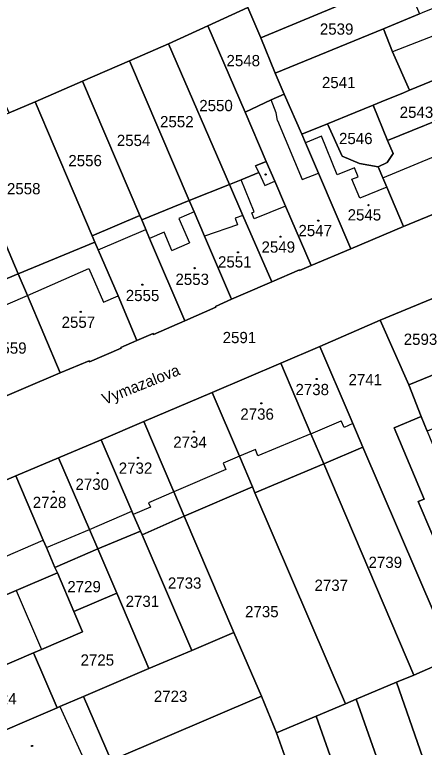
# Model space of a CAD drawing. Extents: x -596233 to -595156, y -1161235 to -1159375.
# Drawn here: x -595764.4 to -595702.6, y -1160730 to -1160619.4 of the extents above; entities that cross this region are included whole.
import ezdxf

# ---------------------------------------------------------------- set-up
doc = ezdxf.new("R2010")
doc.units = 0
for name, color, linetype in [('KN_CAR_KR', 7, 'Continuous'), ('KN_KULTURY', 7, 'Continuous'), ('KN_PARC_CIS_POZ', 7, 'Continuous'), ('KN_PARC_CIS_STAV', 7, 'Continuous'), ('KN_PARC_PLOCHA', 7, 'Continuous'), ('KN_ULICE', 7, 'Continuous'), ('parcely_l', 7, 'Continuous')]:
    doc.layers.add(name, color=color, linetype=linetype)

msp = doc.modelspace()

# ---------------------------------------------------------------- linework, layer by layer
at = {"layer": 'KN_CAR_KR'}
for points in [[(-595695.86, -1160620.52), (-595707.37, -1160625.04)], [(-595724.92, -1160634.21), (-595725.69, -1160632.26)], [(-595724.73, -1160635.4), (-595724.92, -1160634.21)], [(-595724.73, -1160635.4), (-595720.98, -1160644.31)], [(-595718.09, -1160637.77), (-595720.49, -1160638.76)], [(-595715.7, -1160643.59), (-595718.09, -1160637.77)], [(-595708.81, -1160644.05), (-595693.47, -1160637.66)], [(-595727.53, -1160643.25), (-595726.61, -1160645.18)], [(-595720.98, -1160644.31), (-595718.55, -1160643.32)], [(-595713.12, -1160642.53), (-595715.7, -1160643.59)], [(-595712.56, -1160643.88), (-595713.12, -1160642.53)], [(-595728.26, -1160649.17), (-595730.19, -1160644.34)], [(-595726.61, -1160645.18), (-595725.14, -1160644.55)], [(-595713.49, -1160644.26), (-595712.56, -1160643.88)], [(-595712.31, -1160647.13), (-595713.49, -1160644.26)], [(-595708.22, -1160645.45), (-595712.31, -1160647.13)], [(-595723.5, -1160648.34), (-595728.22, -1160650.22)], [(-595737.28, -1160649.19), (-595739.58, -1160650.17)], [(-595729.93, -1160649.73), (-595731.11, -1160650.14)], [(-595728.59, -1160649.3), (-595728.26, -1160649.17)], [(-595728.22, -1160650.22), (-595728.59, -1160649.3)], [(-595739.58, -1160650.17), (-595738.01, -1160653.86)], [(-595730.76, -1160651.14), (-595735.71, -1160652.87)], [(-595731.11, -1160650.14), (-595730.76, -1160651.14)], [(-595751.75, -1160654.9), (-595744.59, -1160651.82)], [(-595741.8, -1160652.24), (-595744.01, -1160653.18)], [(-595740.63, -1160654.99), (-595741.8, -1160652.24)], [(-595740.63, -1160654.99), (-595738.01, -1160653.86)], [(-595762.44, -1160661.8), (-595753.19, -1160657.75)], [(-595753.19, -1160657.75), (-595750.97, -1160662.81)], [(-595771.92, -1160665.87), (-595762.44, -1160661.8)], [(-595750.97, -1160662.81), (-595748.76, -1160661.84)], [(-595719.68, -1160682.67), (-595715.09, -1160680.74)], [(-595714.68, -1160681.73), (-595715.09, -1160680.74)], [(-595713.34, -1160681.15), (-595714.68, -1160681.73)], [(-595719.68, -1160682.67), (-595727.66, -1160686.01)], [(-595728.05, -1160685.08), (-595730.45, -1160686.08)], [(-595727.66, -1160686.01), (-595728.05, -1160685.08)], [(-595730.45, -1160686.08), (-595732.9, -1160687.14)], [(-595732.9, -1160687.14), (-595732.5, -1160688.06)], [(-595732.5, -1160688.06), (-595740.35, -1160691.46)], [(-595740.35, -1160691.46), (-595744.15, -1160693.1)], [(-595744.15, -1160693.1), (-595743.87, -1160693.75)], [(-595753.08, -1160697.13), (-595746.68, -1160694.38)], [(-595743.87, -1160693.75), (-595746.47, -1160694.87)], [(-595759.57, -1160699.85), (-595753.08, -1160697.13)], [(-595767.32, -1160701.86), (-595760.04, -1160698.74)], [(-595764.14, -1160706.35), (-595760.31, -1160715.27)], [(-595757.55, -1160723.87), (-595753.17, -1160733.47)]]:
    msp.add_lwpolyline(points, dxfattribs=at)
at = {"layer": 'KN_KULTURY'}
for centre, radius in [((-595726.51, -1160643.54), 0.09), ((-595726.51, -1160643.54), 0.0398), ((-595711, -1160648.17), 0.09), ((-595711, -1160648.17), 0.0398), ((-595718.57, -1160650.5), 0.09), ((-595718.57, -1160650.5), 0.0398), ((-595724.27, -1160652.93), 0.09), ((-595724.27, -1160652.93), 0.0398), ((-595730.68, -1160655.28), 0.09), ((-595730.68, -1160655.28), 0.0398), ((-595737.22, -1160657.69), 0.09), ((-595737.22, -1160657.69), 0.0398), ((-595745.09, -1160660.18), 0.09), ((-595745.09, -1160660.18), 0.0398), ((-595754.4, -1160664.28), 0.09), ((-595754.4, -1160664.28), 0.0398), ((-595718.81, -1160674.41), 0.09), ((-595718.81, -1160674.41), 0.0398), ((-595727.15, -1160678.09), 0.09), ((-595727.15, -1160678.09), 0.0398), ((-595737.3, -1160682.37), 0.09), ((-595737.3, -1160682.37), 0.0398), ((-595745.75, -1160686.32), 0.09), ((-595745.75, -1160686.32), 0.0398), ((-595751.84, -1160688.63), 0.09), ((-595751.84, -1160688.63), 0.0398), ((-595758.47, -1160691.42), 0.09), ((-595758.47, -1160691.42), 0.0398), ((-595761.73, -1160729.81), 0.09), ((-595761.73, -1160729.81), 0.0398)]:
    msp.add_circle(centre, radius, dxfattribs=at)
at = {"layer": 'KN_PARC_PLOCHA'}
for points in [[(-595735.3, -1160604.49), (-595731.23, -1160613.58), (-595729.21, -1160618.3), (-595735.24, -1160621.08), (-595741.16, -1160623.81), (-595747.02, -1160626.37), (-595754.12, -1160629.47), (-595761.28, -1160632.55), (-595765.17, -1160634.23), (-595770.95, -1160621.41), (-595774.09, -1160614.44), (-595760.01, -1160608.41), (-595748.98, -1160603.72), (-595737.74, -1160599.11), (-595736.97, -1160600.8), (-595736.1, -1160602.72)], [(-595708, -1160614.86), (-595727.25, -1160622.89), (-595729.21, -1160618.3), (-595731.23, -1160613.58), (-595714.79, -1160606.77), (-595711, -1160605.2)], [(-595685.05, -1160622.72), (-595699.52, -1160628.65), (-595704.82, -1160630.82), (-595707.37, -1160625.04), (-595708.75, -1160621.53), (-595703.31, -1160619.29), (-595702.83, -1160619.09), (-595697.24, -1160616.79), (-595688.8, -1160613.32)], [(-595703.31, -1160619.29), (-595708.75, -1160621.53), (-595725.07, -1160628.25), (-595727.25, -1160622.89), (-595708, -1160614.86), (-595705.6, -1160613.86)], [(-595727.25, -1160622.89), (-595725.07, -1160628.25), (-595723.69, -1160631.42), (-595725.69, -1160632.26), (-595729.61, -1160634.15), (-595735.24, -1160621.08), (-595729.21, -1160618.3)], [(-595729.61, -1160634.15), (-595726.42, -1160641.56), (-595728.01, -1160642.25), (-595727.53, -1160643.25), (-595730.19, -1160644.34), (-595731.96, -1160645.05), (-595741.16, -1160623.81), (-595735.24, -1160621.08)], [(-595704.82, -1160630.82), (-595705.72, -1160631.19), (-595709.1, -1160632.57), (-595710.31, -1160633.07), (-595713, -1160634.17), (-595717.18, -1160635.88), (-595721.05, -1160637.47), (-595723.69, -1160631.42), (-595725.07, -1160628.25), (-595708.75, -1160621.53), (-595707.37, -1160625.04)], [(-595731.96, -1160645.05), (-595738.02, -1160647.45), (-595747.02, -1160626.37), (-595741.16, -1160623.81)], [(-595738.02, -1160647.45), (-595745.2, -1160650.39), (-595745.48, -1160649.74), (-595754.12, -1160629.47), (-595747.02, -1160626.37)], [(-595696.11, -1160633.52), (-595696.69, -1160633.76), (-595708.12, -1160638.41), (-595710.31, -1160633.07), (-595709.1, -1160632.57), (-595705.72, -1160631.19), (-595704.82, -1160630.82), (-595699.52, -1160628.65), (-595698.57, -1160630.94), (-595697.19, -1160630.37)], [(-595678.53, -1160638.71), (-595679.29, -1160640.57), (-595682.45, -1160641.9), (-595682.48, -1160641.83), (-595705.69, -1160651.41), (-595708.22, -1160645.45), (-595708.81, -1160644.05), (-595709.52, -1160642.37), (-595708.18, -1160641.71), (-595707.27, -1160640.35), (-595708.12, -1160638.41), (-595696.69, -1160633.76), (-595696.11, -1160633.52), (-595691.34, -1160631.58), (-595682.89, -1160628.14), (-595679.85, -1160635.65), (-595679.77, -1160635.62)], [(-595745.48, -1160649.74), (-595752.65, -1160652.8), (-595761.28, -1160632.55), (-595754.12, -1160629.47)], [(-595721.05, -1160637.47), (-595720.49, -1160638.76), (-595718.55, -1160643.32), (-595713.68, -1160654.78), (-595719.65, -1160657.3), (-595723.5, -1160648.34), (-595725.14, -1160644.55), (-595726.42, -1160641.56), (-595729.61, -1160634.15), (-595725.69, -1160632.26), (-595723.69, -1160631.42)], [(-595752.65, -1160652.8), (-595752.25, -1160653.74), (-595763.83, -1160658.51), (-595772.74, -1160637.53), (-595765.17, -1160634.23), (-595761.28, -1160632.55)], [(-595708.12, -1160638.41), (-595707.27, -1160640.35), (-595708.18, -1160641.71), (-595709.52, -1160642.37), (-595712.35, -1160641.86), (-595714.95, -1160640.78), (-595717.18, -1160635.88), (-595713, -1160634.17), (-595710.31, -1160633.07)], [(-595709.52, -1160642.37), (-595708.81, -1160644.05), (-595708.22, -1160645.45), (-595705.69, -1160651.41), (-595713.68, -1160654.78), (-595718.55, -1160643.32), (-595720.49, -1160638.76), (-595721.05, -1160637.47), (-595717.18, -1160635.88), (-595714.95, -1160640.78), (-595712.35, -1160641.86)], [(-595763.83, -1160658.51), (-595774.97, -1160663.23), (-595777.9, -1160656.33), (-595780.82, -1160649.48), (-595783.88, -1160642.28), (-595772.74, -1160637.53)], [(-595719.65, -1160657.3), (-595721.38, -1160658.03), (-595721.42, -1160657.93), (-595725.59, -1160659.74), (-595729.93, -1160649.73), (-595731.96, -1160645.05), (-595730.19, -1160644.34), (-595727.53, -1160643.25), (-595728.01, -1160642.25), (-595726.42, -1160641.56), (-595725.14, -1160644.55), (-595723.5, -1160648.34)], [(-595725.59, -1160659.74), (-595729.87, -1160661.59), (-595731.65, -1160662.38), (-595735.71, -1160652.87), (-595737.28, -1160649.19), (-595738.02, -1160647.45), (-595731.96, -1160645.05), (-595729.93, -1160649.73)], [(-595731.65, -1160662.38), (-595734.08, -1160663.45), (-595734.02, -1160663.59), (-595738.7, -1160665.63), (-595744.01, -1160653.18), (-595744.59, -1160651.82), (-595745.2, -1160650.39), (-595738.02, -1160647.45), (-595737.28, -1160649.19), (-595735.71, -1160652.87)], [(-595745.2, -1160650.39), (-595744.59, -1160651.82), (-595744.01, -1160653.18), (-595738.7, -1160665.63), (-595743.42, -1160667.69), (-595743.48, -1160667.55), (-595745.91, -1160668.61), (-595748.76, -1160661.84), (-595751.75, -1160654.9), (-595752.25, -1160653.74), (-595752.65, -1160652.8), (-595745.48, -1160649.74)], [(-595745.91, -1160668.61), (-595748.34, -1160669.68), (-595748.3, -1160669.78), (-595753.08, -1160671.81), (-595753.14, -1160671.66), (-595757.48, -1160673.47), (-595762.44, -1160661.8), (-595763.83, -1160658.51), (-595752.25, -1160653.74), (-595751.75, -1160654.9), (-595748.76, -1160661.84)], [(-595757.48, -1160673.47), (-595768.59, -1160678.23), (-595771.39, -1160671.63), (-595772.59, -1160668.83), (-595774.97, -1160663.23), (-595763.83, -1160658.51), (-595762.44, -1160661.8)], [(-595696.04, -1160671.68), (-595704.92, -1160675.31), (-595709.22, -1160665.55), (-595699.97, -1160661.68)], [(-595704.92, -1160675.31), (-595703.06, -1160680.07), (-595707.1, -1160681.78), (-595702.62, -1160692.55), (-595703.52, -1160692.93), (-595699.39, -1160702.59), (-595694.62, -1160700.78), (-595693.12, -1160704.73), (-595690.38, -1160712.25), (-595690.11, -1160713.15), (-595698.19, -1160716.57), (-595711.83, -1160684.68), (-595713.34, -1160681.15), (-595713.75, -1160680.18), (-595718.33, -1160669.48), (-595709.22, -1160665.55)], [(-595686.01, -1160675.72), (-595702.12, -1160682.29), (-595703.06, -1160680.07), (-595704.92, -1160675.31), (-595696.04, -1160671.68), (-595694.19, -1160670.91), (-595688.87, -1160668.73), (-595687.63, -1160671.58)], [(-595711.83, -1160684.68), (-595717.74, -1160687.22), (-595719.68, -1160682.67), (-595724.22, -1160672), (-595718.33, -1160669.48), (-595713.75, -1160680.18), (-595713.34, -1160681.15)], [(-595717.74, -1160687.22), (-595728.11, -1160691.58), (-595728.48, -1160690.69), (-595730.45, -1160686.08), (-595734.58, -1160676.43), (-595724.22, -1160672), (-595719.68, -1160682.67)], [(-595728.48, -1160690.69), (-595738.79, -1160695.14), (-595740.35, -1160691.46), (-595744.88, -1160680.84), (-595734.58, -1160676.43), (-595730.45, -1160686.08)], [(-595738.79, -1160695.14), (-595745.14, -1160697.96), (-595745.38, -1160697.41), (-595746.47, -1160694.87), (-595746.68, -1160694.38), (-595751.31, -1160683.59), (-595744.88, -1160680.84), (-595740.35, -1160691.46)], [(-595702.12, -1160682.29), (-595699.89, -1160687.83), (-595696.29, -1160696.39), (-595694.62, -1160700.78), (-595699.39, -1160702.59), (-595703.52, -1160692.93), (-595702.62, -1160692.55), (-595707.1, -1160681.78), (-595703.06, -1160680.07)], [(-595745.38, -1160697.41), (-595751.83, -1160700.05), (-595753.08, -1160697.13), (-595757.76, -1160686.32), (-595751.31, -1160683.59), (-595746.68, -1160694.38), (-595746.47, -1160694.87)], [(-595698.19, -1160716.57), (-595700.83, -1160717.68), (-595704.17, -1160719.1), (-595717.74, -1160687.22), (-595711.83, -1160684.68)], [(-595751.83, -1160700.05), (-595758.28, -1160702.86), (-595759.57, -1160699.85), (-595760.04, -1160698.74), (-595764.2, -1160689.05), (-595757.76, -1160686.32), (-595753.08, -1160697.13)], [(-595704.17, -1160719.1), (-595706.79, -1160720.2), (-595712.84, -1160722.76), (-595714.48, -1160723.45), (-595728.11, -1160691.58), (-595717.74, -1160687.22)], [(-595758.28, -1160702.86), (-595757.92, -1160703.68), (-595764.14, -1160706.35), (-595765.2, -1160706.8), (-595777.73, -1160712.2), (-595783.98, -1160697.54), (-595764.2, -1160689.05), (-595760.04, -1160698.74), (-595759.57, -1160699.85)], [(-595728.11, -1160691.58), (-595714.48, -1160723.45), (-595718.89, -1160725.32), (-595724.86, -1160727.84), (-595727.15, -1160722.31), (-595731.3, -1160712.67), (-595738.79, -1160695.14), (-595728.48, -1160690.69)], [(-595731.3, -1160712.67), (-595737.66, -1160715.38), (-595745.14, -1160697.96), (-595738.79, -1160695.14)], [(-595745.14, -1160697.96), (-595737.66, -1160715.38), (-595744.11, -1160718.13), (-595748.97, -1160706.75), (-595751.83, -1160700.05), (-595745.38, -1160697.41)], [(-595748.97, -1160706.75), (-595755.42, -1160709.52), (-595757.92, -1160703.68), (-595758.28, -1160702.86), (-595751.83, -1160700.05)], [(-595755.42, -1160709.52), (-595754.1, -1160712.6), (-595760.31, -1160715.27), (-595761.49, -1160715.77), (-595773.94, -1160721.11), (-595777.73, -1160712.2), (-595765.2, -1160706.8), (-595764.14, -1160706.35), (-595757.92, -1160703.68)], [(-595744.11, -1160718.13), (-595753.97, -1160722.33), (-595757.55, -1160723.87), (-595757.97, -1160724.05), (-595761.49, -1160715.77), (-595760.31, -1160715.27), (-595754.1, -1160712.6), (-595755.42, -1160709.52), (-595748.97, -1160706.75)], [(-595727.15, -1160722.31), (-595749.37, -1160731.83), (-595749.78, -1160732.01), (-595753.97, -1160722.33), (-595744.11, -1160718.13), (-595737.66, -1160715.38), (-595731.3, -1160712.67)], [(-595757.97, -1160724.05), (-595770.41, -1160729.4), (-595773.94, -1160721.11), (-595761.49, -1160715.77)], [(-595691.05, -1160745.5), (-595690.33, -1160747.56), (-595696.49, -1160749.65), (-595706.79, -1160720.2), (-595704.17, -1160719.1), (-595700.83, -1160717.68)], [(-595696.49, -1160749.65), (-595702.65, -1160751.74), (-595712.84, -1160722.76), (-595706.79, -1160720.2)], [(-595749.78, -1160732.01), (-595753.17, -1160733.47), (-595766.25, -1160739.11), (-595770.41, -1160729.4), (-595757.97, -1160724.05), (-595757.55, -1160723.87), (-595753.97, -1160722.33)], [(-595724.86, -1160727.84), (-595723.37, -1160732.08), (-595745.36, -1160741.5), (-595749.37, -1160731.83), (-595727.15, -1160722.31)], [(-595702.65, -1160751.74), (-595708.82, -1160753.83), (-595718.89, -1160725.32), (-595714.48, -1160723.45), (-595712.84, -1160722.76)], [(-595708.82, -1160753.83), (-595714.97, -1160756.05), (-595718.37, -1160746.3), (-595720.88, -1160739.16), (-595723.37, -1160732.08), (-595724.86, -1160727.84), (-595718.89, -1160725.32)]]:
    msp.add_lwpolyline(points, close=True, dxfattribs=at)
for points in [[(-595768.59, -1160678.23), (-595757.48, -1160673.47), (-595753.14, -1160671.66), (-595753.08, -1160671.81), (-595748.3, -1160669.78), (-595748.34, -1160669.68), (-595745.91, -1160668.61), (-595743.48, -1160667.55), (-595743.42, -1160667.69), (-595738.7, -1160665.63), (-595734.02, -1160663.59), (-595734.08, -1160663.45), (-595731.65, -1160662.38), (-595729.87, -1160661.59), (-595725.59, -1160659.74), (-595721.42, -1160657.93), (-595721.38, -1160658.03), (-595719.65, -1160657.3), (-595713.68, -1160654.78), (-595705.69, -1160651.41), (-595682.48, -1160641.83)], [(-595699.97, -1160661.68), (-595709.22, -1160665.55), (-595718.33, -1160669.48), (-595724.22, -1160672), (-595734.58, -1160676.43), (-595744.88, -1160680.84), (-595751.31, -1160683.59), (-595757.76, -1160686.32), (-595764.2, -1160689.05), (-595783.98, -1160697.54)]]:
    msp.add_lwpolyline(points, dxfattribs=at)
at = {"layer": 'parcely_l'}
for points in [[(-595708, -1160614.86), (-595727.25, -1160622.89)], [(-595735.24, -1160621.08), (-595729.21, -1160618.3)], [(-595727.25, -1160622.89), (-595729.21, -1160618.3)], [(-595703.31, -1160619.29), (-595708.75, -1160621.53)], [(-595735.24, -1160621.08), (-595741.16, -1160623.81)], [(-595729.61, -1160634.15), (-595735.24, -1160621.08)], [(-595708.75, -1160621.53), (-595725.07, -1160628.25)], [(-595704.82, -1160630.82), (-595707.37, -1160625.04), (-595708.75, -1160621.53)], [(-595727.25, -1160622.89), (-595725.07, -1160628.25)], [(-595741.16, -1160623.81), (-595747.02, -1160626.37)], [(-595731.96, -1160645.05), (-595741.16, -1160623.81)], [(-595754.12, -1160629.47), (-595747.02, -1160626.37)], [(-595747.02, -1160626.37), (-595738.02, -1160647.45)], [(-595725.07, -1160628.25), (-595723.69, -1160631.42)], [(-595704.82, -1160630.82), (-595699.52, -1160628.65)], [(-595754.12, -1160629.47), (-595761.28, -1160632.55)], [(-595745.48, -1160649.74), (-595754.12, -1160629.47)], [(-595710.31, -1160633.07), (-595709.1, -1160632.57), (-595705.72, -1160631.19), (-595704.82, -1160630.82)], [(-595729.61, -1160634.15), (-595725.69, -1160632.26), (-595723.69, -1160631.42)], [(-595723.69, -1160631.42), (-595721.05, -1160637.47)], [(-595761.28, -1160632.55), (-595765.17, -1160634.23)], [(-595761.28, -1160632.55), (-595752.65, -1160652.8)], [(-595717.18, -1160635.88), (-595713, -1160634.17), (-595710.31, -1160633.07)], [(-595710.31, -1160633.07), (-595708.12, -1160638.41)], [(-595708.12, -1160638.41), (-595696.69, -1160633.76), (-595696.11, -1160633.52)], [(-595726.42, -1160641.56), (-595729.61, -1160634.15)], [(-595721.05, -1160637.47), (-595717.18, -1160635.88)], [(-595709.52, -1160642.37), (-595712.35, -1160641.86), (-595714.95, -1160640.78), (-595717.18, -1160635.88)], [(-595763.83, -1160658.51), (-595772.74, -1160637.53)], [(-595721.05, -1160637.47), (-595720.49, -1160638.76), (-595718.55, -1160643.32), (-595713.68, -1160654.78)], [(-595708.12, -1160638.41), (-595707.27, -1160640.35), (-595708.18, -1160641.71), (-595709.52, -1160642.37)], [(-595705.69, -1160651.41), (-595682.48, -1160641.83), (-595682.45, -1160641.9), (-595679.29, -1160640.57), (-595678.53, -1160638.71)], [(-595731.96, -1160645.05), (-595730.19, -1160644.34), (-595727.53, -1160643.25), (-595728.01, -1160642.25), (-595726.42, -1160641.56)], [(-595719.65, -1160657.3), (-595723.5, -1160648.34), (-595725.14, -1160644.55), (-595726.42, -1160641.56)], [(-595709.52, -1160642.37), (-595708.81, -1160644.05), (-595708.22, -1160645.45), (-595705.69, -1160651.41)], [(-595738.02, -1160647.45), (-595731.96, -1160645.05)], [(-595731.96, -1160645.05), (-595729.93, -1160649.73), (-595725.59, -1160659.74)], [(-595738.02, -1160647.45), (-595745.2, -1160650.39)], [(-595731.65, -1160662.38), (-595735.71, -1160652.87), (-595737.28, -1160649.19), (-595738.02, -1160647.45)], [(-595752.65, -1160652.8), (-595745.48, -1160649.74)], [(-595745.2, -1160650.39), (-595745.48, -1160649.74)], [(-595738.7, -1160665.63), (-595744.01, -1160653.18), (-595744.59, -1160651.82), (-595745.2, -1160650.39)], [(-595713.68, -1160654.78), (-595705.69, -1160651.41)], [(-595752.25, -1160653.74), (-595752.65, -1160652.8)], [(-595763.83, -1160658.51), (-595752.25, -1160653.74)], [(-595752.25, -1160653.74), (-595751.75, -1160654.9), (-595748.76, -1160661.84), (-595745.91, -1160668.61)], [(-595713.68, -1160654.78), (-595719.65, -1160657.3)], [(-595725.59, -1160659.74), (-595721.42, -1160657.93), (-595721.38, -1160658.03), (-595719.65, -1160657.3)], [(-595763.83, -1160658.51), (-595774.97, -1160663.23)], [(-595757.48, -1160673.47), (-595762.44, -1160661.8), (-595763.83, -1160658.51)], [(-595725.59, -1160659.74), (-595729.87, -1160661.59), (-595731.65, -1160662.38)], [(-595699.97, -1160661.68), (-595709.22, -1160665.55)], [(-595738.7, -1160665.63), (-595734.02, -1160663.59), (-595734.08, -1160663.45), (-595731.65, -1160662.38)], [(-595709.22, -1160665.55), (-595718.33, -1160669.48)], [(-595709.22, -1160665.55), (-595704.92, -1160675.31)], [(-595745.91, -1160668.61), (-595743.48, -1160667.55), (-595743.42, -1160667.69), (-595738.7, -1160665.63)], [(-595757.48, -1160673.47), (-595753.14, -1160671.66), (-595753.08, -1160671.81), (-595748.3, -1160669.78), (-595748.34, -1160669.68), (-595745.91, -1160668.61)], [(-595718.33, -1160669.48), (-595724.22, -1160672)], [(-595711.83, -1160684.68), (-595713.34, -1160681.15), (-595713.75, -1160680.18), (-595718.33, -1160669.48)], [(-595724.22, -1160672), (-595734.58, -1160676.43)], [(-595724.22, -1160672), (-595719.68, -1160682.67), (-595717.74, -1160687.22)], [(-595704.92, -1160675.31), (-595696.04, -1160671.68)], [(-595768.59, -1160678.23), (-595757.48, -1160673.47)], [(-595704.92, -1160675.31), (-595703.06, -1160680.07)], [(-595744.88, -1160680.84), (-595734.58, -1160676.43)], [(-595734.58, -1160676.43), (-595730.45, -1160686.08), (-595728.48, -1160690.69)], [(-595744.88, -1160680.84), (-595751.31, -1160683.59)], [(-595738.79, -1160695.14), (-595740.35, -1160691.46), (-595744.88, -1160680.84)], [(-595703.06, -1160680.07), (-595707.1, -1160681.78), (-595702.62, -1160692.55), (-595703.52, -1160692.93), (-595699.39, -1160702.59), (-595694.62, -1160700.78)], [(-595702.12, -1160682.29), (-595703.06, -1160680.07)], [(-595751.31, -1160683.59), (-595757.76, -1160686.32)], [(-595751.31, -1160683.59), (-595746.68, -1160694.38), (-595746.47, -1160694.87), (-595745.38, -1160697.41)], [(-595717.74, -1160687.22), (-595711.83, -1160684.68)], [(-595698.19, -1160716.57), (-595711.83, -1160684.68)], [(-595757.76, -1160686.32), (-595764.2, -1160689.05)], [(-595751.83, -1160700.05), (-595753.08, -1160697.13), (-595757.76, -1160686.32)], [(-595717.74, -1160687.22), (-595728.11, -1160691.58)], [(-595717.74, -1160687.22), (-595704.17, -1160719.1)], [(-595783.98, -1160697.54), (-595764.2, -1160689.05)], [(-595764.2, -1160689.05), (-595760.04, -1160698.74), (-595759.57, -1160699.85), (-595758.28, -1160702.86)], [(-595728.48, -1160690.69), (-595738.79, -1160695.14)], [(-595728.11, -1160691.58), (-595728.48, -1160690.69)], [(-595728.11, -1160691.58), (-595714.48, -1160723.45)], [(-595745.14, -1160697.96), (-595738.79, -1160695.14)], [(-595738.79, -1160695.14), (-595731.3, -1160712.67)], [(-595745.38, -1160697.41), (-595751.83, -1160700.05)], [(-595745.14, -1160697.96), (-595745.38, -1160697.41)], [(-595737.66, -1160715.38), (-595745.14, -1160697.96)], [(-595758.28, -1160702.86), (-595751.83, -1160700.05)], [(-595751.83, -1160700.05), (-595748.97, -1160706.75)], [(-595758.28, -1160702.86), (-595757.92, -1160703.68)], [(-595757.92, -1160703.68), (-595764.14, -1160706.35), (-595765.2, -1160706.8), (-595777.73, -1160712.2)], [(-595755.42, -1160709.52), (-595757.92, -1160703.68)], [(-595755.42, -1160709.52), (-595748.97, -1160706.75)], [(-595748.97, -1160706.75), (-595744.11, -1160718.13)], [(-595761.49, -1160715.77), (-595760.31, -1160715.27), (-595754.1, -1160712.6), (-595755.42, -1160709.52)], [(-595731.3, -1160712.67), (-595737.66, -1160715.38)], [(-595731.3, -1160712.67), (-595727.15, -1160722.31)], [(-595744.11, -1160718.13), (-595737.66, -1160715.38)], [(-595773.94, -1160721.11), (-595761.49, -1160715.77)], [(-595761.49, -1160715.77), (-595757.97, -1160724.05)], [(-595753.97, -1160722.33), (-595744.11, -1160718.13)], [(-595704.17, -1160719.1), (-595700.83, -1160717.68)], [(-595706.79, -1160720.2), (-595704.17, -1160719.1)], [(-595712.84, -1160722.76), (-595706.79, -1160720.2)], [(-595696.49, -1160749.65), (-595706.79, -1160720.2)], [(-595753.97, -1160722.33), (-595757.55, -1160723.87), (-595757.97, -1160724.05)], [(-595749.78, -1160732.01), (-595753.97, -1160722.33)], [(-595727.15, -1160722.31), (-595749.37, -1160731.83)], [(-595727.15, -1160722.31), (-595724.86, -1160727.84)], [(-595714.48, -1160723.45), (-595712.84, -1160722.76)], [(-595712.84, -1160722.76), (-595702.65, -1160751.74)], [(-595757.97, -1160724.05), (-595770.41, -1160729.4)], [(-595718.89, -1160725.32), (-595714.48, -1160723.45)], [(-595724.86, -1160727.84), (-595718.89, -1160725.32)], [(-595708.82, -1160753.83), (-595718.89, -1160725.32)], [(-595724.86, -1160727.84), (-595723.37, -1160732.08)]]:
    msp.add_lwpolyline(points, dxfattribs=at)

# ---------------------------------------------------------------- texts
at = {"layer": 'KN_PARC_CIS_POZ'}
for s, p in [('2539', (-595718.3266, -1160622.43)), ('2548', (-595732.4066, -1160627.19)), ('2541', (-595718.0166, -1160630.5)), ('2550', (-595736.5166, -1160633.98)), ('2543', (-595706.2866, -1160634.99)), ('2552', (-595742.4266, -1160636.41)), ('2554', (-595748.9466, -1160639.24)), ('2546', (-595715.4366, -1160638.95)), ('2556', (-595756.2566, -1160642.29)), ('2558', (-595765.5166, -1160646.53)), ('2591', (-595732.9866, -1160669)), ('2593', (-595705.6766, -1160669.26)), ('2741', (-595714.0066, -1160675.37)), ('2739', (-595710.9866, -1160702.94)), ('2729', (-595756.4166, -1160706.61)), ('2733', (-595741.2466, -1160706.07)), ('2737', (-595719.1366, -1160706.4)), ('2731', (-595747.6266, -1160708.82)), ('2735', (-595729.6066, -1160710.38)), ('2725', (-595754.4166, -1160717.69)), ('2723', (-595743.3666, -1160723.16))]:
    msp.add_text(s, height=1.7, dxfattribs=at).set_placement(p)
at = {"layer": 'KN_PARC_CIS_STAV'}
for s, p in [('2545', (-595714.1366, -1160650.48)), ('2547', (-595721.5566, -1160652.85)), ('2549', (-595727.1266, -1160655.34)), ('2551', (-595733.6866, -1160657.58)), ('2553', (-595740.1066, -1160660.21)), ('2555', (-595747.5966, -1160662.65)), ('2557', (-595757.2766, -1160666.69)), ('2559', (-595767.6166, -1160670.59)), ('2738', (-595722.0066, -1160676.85)), ('2736', (-595730.3166, -1160680.56)), ('2734', (-595740.4366, -1160684.8)), ('2732', (-595748.6566, -1160688.72)), ('2730', (-595755.1866, -1160691.15)), ('2728', (-595761.6266, -1160693.89)), ('2724', (-595769.1166, -1160723.52))]:
    msp.add_text(s, height=1.7, dxfattribs=at).set_placement(p)
at = {"layer": 'KN_ULICE'}
msp.add_text('Vymazalova', height=1.7, rotation=21.841965, dxfattribs=at).set_placement((-595750.7667, -1160678.327))

doc.saveas('drawing.dxf')
